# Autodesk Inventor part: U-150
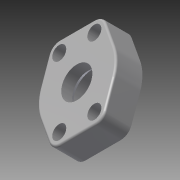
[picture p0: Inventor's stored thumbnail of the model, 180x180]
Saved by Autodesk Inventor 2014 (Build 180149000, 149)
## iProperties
Created: 2011-01
Part Number: U-150
Material: Steel
Document SubType Name: Modeling
Designer: deckm
Density: 7.85 g/cm^3
Description: FLARED FLANGE SAE WITH CLEARANCE HOLES
Mass: 259.498 g
Surface Area: 100.719 cm^2
Volume: 33.0571 cm^3
Appearance: Steel
Author: deckm
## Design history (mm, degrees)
derived "union_cap.ipt"
body "Solid1"
feature "Solid1::union_cap.ipt"
tag "TaggingFeature1"
other parameters: "d1" = 92.964, "d3" = 19.10263, "d25" = 35.814, "FilletTop" = 2, "d27" = 19.05, "d28" = 37 deg, "d29" = 26.924, "d30" = 15.875, "FilletCorners" = 11.557, "FilletEnds" = 41.275, "d8" = 26.924, "d9" = 0, "d12" = 14.2875, "d21" = 35.814, "d24" = 69.85
